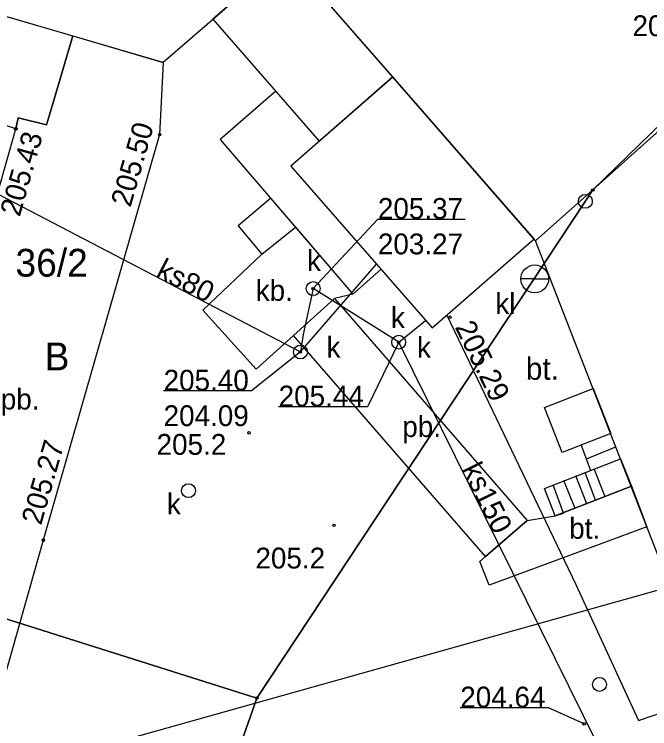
# Model space of a CAD drawing. Extents: x 6512400 to 6513200, y 6022500 to 6022750.
# Drawn here: x 6512810.71 to 6512833.59, y 6022608.68 to 6022634.38 of the extents above; entities that cross this region are included whole.
import ezdxf

# ---------------------------------------------------------------- set-up
doc = ezdxf.new("R2010")
doc.units = 0
for name, color, linetype in [('202-punkt graniczny', 7, 'Continuous'), ('203-punkt graniczny', 7, 'Continuous'), ('210-oznaczenie konturu użytku gruntowego', 7, 'Continuous'), ('211-numer działki ewidencyjnej', 7, 'Continuous'), ('217-kontur klasyfikacyjny', 7, 'Continuous'), ('218-kontur użytku gruntowego', 7, 'Continuous'), ('219-działka ewidencyjna', 7, 'Continuous'), ('312-budynek ewidencyjny', 7, 'Continuous'), ('352-schody', 7, 'Continuous'), ('423-Schody przy drogach  chodnikach', 7, 'Continuous'), ('chodnik', 7, 'Continuous'), ('Komentarz lub etykieta na mapie', 7, 'Continuous'), ('Obszar opracowania', 7, 'Continuous'), ('obszar utwardzony', 7, 'Continuous'), ('obszar utwardzony-Atr17', 7, 'Continuous'), ('osadnik kanalizacji lokalnej (dół Chambeau) (punkt)', 7, 'Continuous'), ('osadnik kanalizacji lokalnej (dół Chambeau) (punkt)-Atr17', 7, 'Continuous'), ('pikieta sztuczna', 7, 'Continuous'), ('pikieta sztuczna-Atr2', 7, 'Continuous'), ('podpora związana z budynkiem (punkt)', 7, 'Continuous'), ('przewód gazowy (linia)', 7, 'Continuous'), ('przewód kanalizacyjny (linia)', 7, 'Continuous'), ('przewód kanalizacyjny (linia)-Atr1', 7, 'Continuous'), ('punkt o określonej wysokości (sieć gazowa)', 7, 'Continuous'), ('punkt o określonej wysokości (sieć gazowa)-Atr2', 7, 'Continuous'), ('punkt o określonej wysokości (sieć kanalizacyjna)', 7, 'Continuous'), ('punkt o określonej wysokości (sieć kanalizacyjna)-Atr2', 7, 'Continuous'), ('punkt o określonej wysokości (sieć kanalizacyjna)-Atr3', 7, 'Continuous'), ('punkt o określonej wysokości (sieć wodociągowa)-Atr3', 7, 'Continuous'), ('punkt wysokościowy naturalny', 7, 'Continuous'), ('punkt wysokościowy naturalny-Atr2', 7, 'Continuous'), ('studnia kanalizacyjna', 7, 'Continuous'), ('studnia kanalizacyjna-Atr17', 7, 'Continuous'), ('właz okrągły - siec kanalizacyjna (punkt)', 7, 'Continuous'), ('właz okrągły - siec kanalizacyjna (punkt)-Atr17', 7, 'Continuous')]:
    doc.layers.add(name, color=color, linetype=linetype)

# ---------------------------------------------------------------- blocks, each defined once
blk = doc.blocks.new('203')
blk.add_circle((0, 0), 0.045)
blk = doc.blocks.new('202')
blk.add_circle((0, 0), 0.25)
blk = doc.blocks.new('PW01')
blk.add_circle((0, 0), 0.045)
blk = doc.blocks.new('US22')
blk.add_circle((0, 0), 0.25)
blk = doc.blocks.new('US07')
for q in [(-0.5, 0), (0.5, 0)]:
    blk.add_line((0, 0), q)
blk.add_circle((0, 0), 0.5)
blk = doc.blocks.new('IB04')
blk.add_circle((0, 0), 0.25)
blk = doc.blocks.new('US15')
blk.add_circle((0, 0), 0.25)

msp = doc.modelspace()

# ---------------------------------------------------------------- linework, layer by layer
at = {"layer": '217-kontur klasyfikacyjny'}
for points in [[(6512837.41, 6022633.76), (6512831.54, 6022628.06)], [(6512831.54, 6022628.06), (6512831.27, 6022627.65)], [(6512831.27, 6022627.65), (6512819.44, 6022609.78)], [(6512819.44, 6022609.78), (6512811.09, 6022586.02)]]:
    msp.add_lwpolyline(points, dxfattribs=at)
at = {"layer": '218-kontur użytku gruntowego'}
for points in [[(6512831.54, 6022628.06), (6512837.41, 6022633.76)], [(6512837.41, 6022633.76), (6512831.54, 6022628.06)], [(6512831.27, 6022627.65), (6512831.54, 6022628.06)], [(6512831.54, 6022628.06), (6512831.27, 6022627.65)], [(6512819.44, 6022609.78), (6512831.27, 6022627.65)], [(6512831.27, 6022627.65), (6512819.44, 6022609.78)], [(6512792.55, 6022618.27), (6512819.44, 6022609.78)], [(6512819.44, 6022609.78), (6512792.55, 6022618.27)], [(6512819.44, 6022609.78), (6512811.09, 6022586.02)], [(6512811.09, 6022586.02), (6512819.44, 6022609.78)]]:
    msp.add_lwpolyline(points, dxfattribs=at)
at = {"layer": '219-działka ewidencyjna'}
for points in [[(6512831.54, 6022628.06), (6512837.41, 6022633.76)], [(6512831.54, 6022628.06), (6512831.27, 6022627.65)], [(6512831.27, 6022627.65), (6512819.44, 6022609.78)], [(6512819.44, 6022609.78), (6512792.55, 6022618.27)], [(6512819.44, 6022609.78), (6512811.09, 6022586.02)]]:
    msp.add_lwpolyline(points, dxfattribs=at)
at = {"layer": '312-budynek ewidencyjny'}
for points in [[(6512821.69, 6022629.82), (6512824.34, 6022632.13), (6512820.51, 6022636.51), (6512817.86, 6022634.2)], [(6512825.76, 6022623.1), (6512829.43, 6022626.3), (6512824.34, 6022632.13), (6512820.67, 6022628.92)]]:
    msp.add_lwpolyline(points, close=True, dxfattribs=at)
for points in [[(6512820.51, 6022636.51), (6512817.92, 6022634.24)], [(6512824.19, 6022632.29), (6512820.51, 6022636.51)], [(6512816.07, 6022632.65), (6512802.96, 6022636.48)], [(6512817.92, 6022634.24), (6512816.07, 6022632.65)], [(6512837.59, 6022633.47), (6512831.54, 6022628.06)], [(6512831.54, 6022628.06), (6512837.59, 6022633.47)], [(6512829.48, 6022626.23), (6512824.19, 6022632.29)], [(6512820.13, 6022631.61), (6512818.12, 6022629.87), (6512822.9, 6022624.31), (6512823.92, 6022625.21)], [(6512831.54, 6022628.06), (6512829.48, 6022626.23)], [(6512829.48, 6022626.23), (6512831.54, 6022628.06)], [(6512819.94, 6022627.76), (6512818.77, 6022626.77), (6512819.62, 6022625.75), (6512820.83, 6022626.72)], [(6512835.06, 6022611.91), (6512829.48, 6022626.23)]]:
    msp.add_lwpolyline(points, dxfattribs=at)
at = {"layer": '352-schody'}
for p, q in [((6512831.12, 6022618.88), (6512831.46, 6022617.97)), ((6512831.31, 6022618.38), (6512832.37, 6022618.82))]:
    msp.add_line(p, q, dxfattribs=at)
at = {"layer": '423-Schody przy drogach  chodnikach'}
for p, q in [((6512829.8, 6022620.23), (6512831.55, 6022620.92)), ((6512831.55, 6022620.92), (6512832.19, 6022619.3)), ((6512830.44, 6022618.61), (6512829.8, 6022620.23)), ((6512832.19, 6022619.3), (6512830.44, 6022618.61)), ((6512829.8, 6022617.32), (6512832.54, 6022618.39)), ((6512832.54, 6022618.39), (6512832.93, 6022617.4)), ((6512831.99, 6022617.02), (6512831.59, 6022618.03)), ((6512831.32, 6022616.77), (6512830.93, 6022617.77)), ((6512831.64, 6022616.9), (6512831.26, 6022617.89)), ((6512830.9, 6022616.6), (6512830.5, 6022617.6)), ((6512830.19, 6022616.33), (6512829.8, 6022617.32)), ((6512830.48, 6022616.43), (6512830.11, 6022617.45)), ((6512832.93, 6022617.4), (6512830.19, 6022616.33)), ((6512830.19, 6022616.33), (6512830.48, 6022616.43))]:
    msp.add_line(p, q, dxfattribs=at)
at = {"layer": 'chodnik'}
msp.add_lwpolyline([(6512795.99, 6022610.57), (6512799.35, 6022621.32), (6512803.99, 6022636.18), (6512812.81, 6022633.6), (6512812.08, 6022631.12), (6512811.87, 6022630.4), (6512810.85, 6022630.66), (6512810.76, 6022630.26), (6512803.86, 6022632.53), (6512801.71, 6022625.65), (6512801.45, 6022624.81), (6512799.88, 6022619.78), (6512799.6, 6022618.92), (6512796.91, 6022610.28)], close=True, dxfattribs=at)
at = {"layer": 'Obszar opracowania'}
msp.add_lwpolyline([(6512710.98, 6022693.84), (6512748.35, 6022694.16), (6512798.11, 6022695.25), (6512807.47, 6022695.46), (6512809.66, 6022606.87), (6512863.71, 6022622.03), (6512875.13, 6022581.36), (6512755.22, 6022535.25), (6512691.61, 6022568.03), (6512709.16, 6022605.16)], close=True, dxfattribs=at)
at = {"layer": 'obszar utwardzony'}
for points in [[(6512812.81, 6022633.6), (6512816.07, 6022632.65), (6512815.94, 6022630.05), (6512811.75, 6022615.46), (6512809.03, 6022605.91), (6512807.28, 6022599.67), (6512817.34, 6022602.22), (6512825.55, 6022604.37), (6512836.54, 6022607.78), (6512838.38, 6022602.97), (6512827.08, 6022599.6), (6512818.35, 6022597.29), (6512807.91, 6022594.59), (6512801.11, 6022596.47), (6512802.38, 6022600.88), (6512804.17, 6022607.14), (6512806.87, 6022616.66), (6512807.12, 6022617.53), (6512808.57, 6022622.5), (6512808.8, 6022623.37), (6512810.76, 6022630.26), (6512810.85, 6022630.66), (6512811.87, 6022630.4), (6512812.08, 6022631.12)], [(6512819.62, 6022625.75), (6512820.83, 6022626.72), (6512822.9, 6022624.31), (6512822.24, 6022624.16), (6512820.76, 6022622.82), (6512819.42, 6022621.61), (6512817.49, 6022623.73)], [(6512820.76, 6022622.82), (6512822.24, 6022624.16), (6512829.18, 6022616.17), (6512827.67, 6022614.87)], [(6512832.93, 6022617.4), (6512833.49, 6022615.94), (6512830.57, 6022614.86), (6512827.81, 6022613.84), (6512827.47, 6022614.69), (6512827.67, 6022614.87), (6512829.18, 6022616.17), (6512830.19, 6022616.33)]]:
    msp.add_lwpolyline(points, close=True, dxfattribs=at)
at = {"layer": 'przewód gazowy (linia)'}
msp.add_lwpolyline([(6512826.28, 6022623.56), (6512830.93, 6022613.86), (6512833.19, 6022608.97), (6512847.18, 6022613.76), (6512847.79, 6022614.02)], dxfattribs=at)
at = {"layer": 'przewód kanalizacyjny (linia)'}
for points in [[(6512808.18, 6022628.91), (6512821.01, 6022622.23)], [(6512821.01, 6022622.23), (6512823.75, 6022625.39)], [(6512821.47, 6022624.51), (6512821.11, 6022622.86), (6512821.01, 6022622.23)], [(6512824.55, 6022622.58), (6512821.47, 6022624.51)], [(6512824.55, 6022622.58), (6512825.52, 6022623.36)], [(6512832.23, 6022607.08), (6512824.55, 6022622.58)]]:
    msp.add_lwpolyline(points, dxfattribs=at)
at = {"layer": 'punkt o określonej wysokości (sieć kanalizacyjna)-Atr2'}
for points in [[(6512821.47, 6022624.51), (6512823.8, 6022627.01), (6512826.946, 6022627.01)], [(6512824.55, 6022622.58), (6512823.43, 6022620.26), (6512820.226, 6022620.26)], [(6512821.01, 6022622.23), (6512819.25, 6022620.83), (6512816.083, 6022620.83)], [(6512831.23, 6022608.85), (6512829.94, 6022609.43), (6512826.767, 6022609.43)]]:
    msp.add_lwpolyline(points, dxfattribs=at)

# ---------------------------------------------------------------- block references
at = {"layer": '202-punkt graniczny'}
msp.add_blockref('202', (6512831.27, 6022627.65), dxfattribs=at)
at = {"layer": '203-punkt graniczny'}
for p in [(6512831.54, 6022628.06), (6512819.44, 6022609.78)]:
    msp.add_blockref('203', p, dxfattribs=at)
at = {"layer": 'osadnik kanalizacji lokalnej (dół Chambeau) (punkt)'}
msp.add_blockref('US07', (6512829.45, 6022624.86), dxfattribs=at)
at = {"layer": 'pikieta sztuczna'}
for p in [(6512810.76, 6022630.26), (6512815.94, 6022630.05), (6512811.75, 6022615.46)]:
    msp.add_blockref('PW01', p, dxfattribs=at)
at = {"layer": 'podpora związana z budynkiem (punkt)'}
for p in [(6512824.55, 6022622.58), (6512831.78, 6022610.27)]:
    msp.add_blockref('IB04', p, dxfattribs=at)
at = {"layer": 'punkt o określonej wysokości (sieć gazowa)'}
msp.add_blockref('PW01', (6512826.4, 6022623.48), dxfattribs=at)
at = {"layer": 'punkt o określonej wysokości (sieć kanalizacyjna)'}
for p in [(6512821.47, 6022624.51), (6512824.55, 6022622.58), (6512831.23, 6022608.85)]:
    msp.add_blockref('PW01', p, dxfattribs=at)
at = {"layer": 'punkt o określonej wysokości (sieć kanalizacyjna)', "rotation": -30.519000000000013}
msp.add_blockref('PW01', (6512821.01, 6022622.23), dxfattribs=at)
at = {"layer": 'punkt wysokościowy naturalny'}
for p in [(6512819.16, 6022619.32), (6512822.22, 6022615.99)]:
    msp.add_blockref('PW01', p, dxfattribs=at)
at = {"layer": 'studnia kanalizacyjna'}
for p in [(6512824.55, 6022622.58), (6512816.98, 6022617.24)]:
    msp.add_blockref('US15', p, dxfattribs=at)
at = {"layer": 'właz okrągły - siec kanalizacyjna (punkt)'}
for p in [(6512821.47, 6022624.51), (6512824.55, 6022622.58)]:
    msp.add_blockref('US22', p, dxfattribs=at)
at = {"layer": 'właz okrągły - siec kanalizacyjna (punkt)', "rotation": -30.519000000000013}
msp.add_blockref('US22', (6512821.01, 6022622.23), dxfattribs=at)

# ---------------------------------------------------------------- texts
at = {"layer": '210-oznaczenie konturu użytku gruntowego'}
msp.add_text('B', height=1, dxfattribs=at).set_placement((6512811.8, 6022621.57))
at = {"layer": '211-numer działki ewidencyjnej'}
msp.add_text('36/2', height=1, dxfattribs=at).set_placement((6512810.75, 6022624.94))
at = {"layer": 'Komentarz lub etykieta na mapie'}
msp.add_text('bt.', height=0.8, dxfattribs=at).set_placement((6512829.13, 6022621.23))
at = {"layer": 'obszar utwardzony-Atr17'}
for s, p in [('kb.', (6512819.4, 6022624.07)), ('pb.', (6512810.22, 6022620.16)), ('pb.', (6512824.68, 6022619.17)), ('bt.', (6512830.69, 6022615.51))]:
    msp.add_text(s, height=0.75, dxfattribs=at).set_placement(p)
at = {"layer": 'osadnik kanalizacji lokalnej (dół Chambeau) (punkt)-Atr17'}
msp.add_text('kl', height=0.75, dxfattribs=at).set_placement((6512828.03, 6022623.6))
at = {"layer": 'pikieta sztuczna-Atr2'}
for s, rotation, p in [('205.50', 73.977, (6512814.89, 6022627.41)), ('205.43', 74.121, (6512810.9, 6022627.07)), ('205.27', 73.977, (6512811.67, 6022615.97))]:
    msp.add_text(s, height=0.75, rotation=rotation, dxfattribs=at).set_placement(p)
at = {"layer": 'przewód kanalizacyjny (linia)-Atr1'}
for s, rotation, p in [('ks80', 332.496, (6512815.77, 6022624.96)), ('ks150', 296.358, (6512826.81, 6022618.02))]:
    msp.add_text(s, height=0.75, rotation=rotation, dxfattribs=at).set_placement(p)
at = {"layer": 'punkt o określonej wysokości (sieć gazowa)-Atr2'}
msp.add_text('205.29', height=0.75, rotation=296.046, dxfattribs=at).set_placement((6512826.56, 6022623.13))
at = {"layer": 'punkt o określonej wysokości (sieć kanalizacyjna)-Atr2'}
for s, p in [('205.37', (6512823.8, 6022627.018)), ('205.40', (6512816.083, 6022620.838)), ('205.44', (6512820.226, 6022620.268)), ('204.64', (6512826.767, 6022609.438))]:
    msp.add_text(s, height=0.75, dxfattribs=at).set_placement(p)
msp.add_text('204.64', height=0.75, rotation=21.531, dxfattribs=at).set_placement((6512832.8, 6022607.3))
at = {"layer": 'punkt o określonej wysokości (sieć kanalizacyjna)-Atr3'}
for s, p in [('203.27', (6512823.8, 6022625.742)), ('204.09', (6512816.083, 6022619.562))]:
    msp.add_text(s, height=0.75, dxfattribs=at).set_placement(p)
at = {"layer": 'punkt o określonej wysokości (sieć wodociągowa)-Atr3'}
msp.add_text('204.89', height=0.75, dxfattribs=at).set_placement((6512832.969, 6022633.593))
at = {"layer": 'punkt wysokościowy naturalny-Atr2'}
for p in [(6512815.83, 6022618.53), (6512819.39, 6022614.44)]:
    msp.add_text('205.2', height=0.75, dxfattribs=at).set_placement(p)
at = {"layer": 'studnia kanalizacyjna-Atr17'}
for p in [(6512825.21, 6022622.02), (6512816.2, 6022616.39)]:
    msp.add_text('k', height=0.75, dxfattribs=at).set_placement(p)
at = {"layer": 'właz okrągły - siec kanalizacyjna (punkt)-Atr17'}
for p in [(6512821.25, 6022625.14), (6512824.27, 6022623.09), (6512821.95, 6022622.03)]:
    msp.add_text('k', height=0.75, dxfattribs=at).set_placement(p)

doc.saveas('drawing.dxf')
